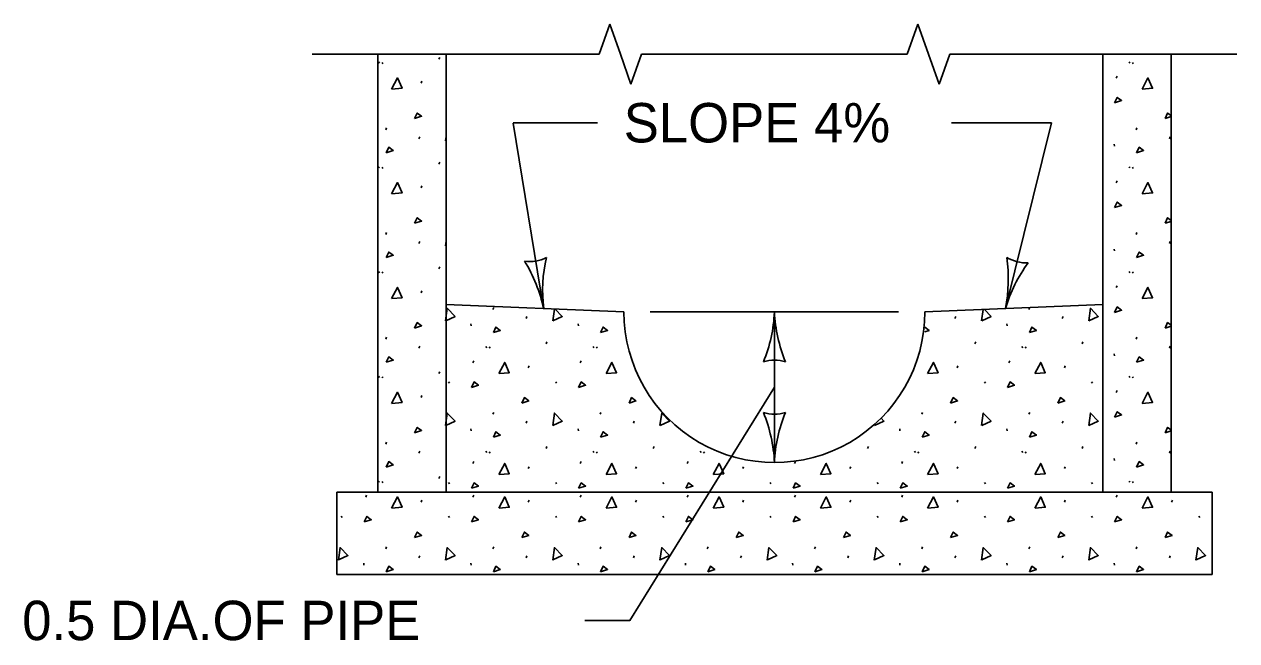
# Model space of a CAD drawing. Extents: x 49991.4 to 50028.3, y 49987.6 to 50011.4.
# Drawn here: x 50021.035 to 50022.881, y 49996.665 to 49997.603 of the extents above; entities that cross this region are included whole.
import ezdxf

# ---------------------------------------------------------------- set-up
doc = ezdxf.new("R2010")
doc.units = 0
for name, color, linetype in [('Level 1', 7, 'Continuous'), ('Level 2', 7, 'Continuous'), ('Level 3', 7, 'Continuous'), ('Level 6', 7, 'Continuous')]:
    doc.layers.add(name, color=color, linetype=linetype)

msp = doc.modelspace()

# ---------------------------------------------------------------- linework, layer by layer
at = {"layer": 'Level 1'}
for p, q in [((50021.5732, 49996.8908), (50021.5732, 49997.5575)), ((50021.6773, 49997.5575), (50021.6773, 49996.8908)), ((50022.6773, 49996.8908), (50022.6773, 49997.5575)), ((50022.7814, 49997.5575), (50022.7814, 49996.8908)), ((50021.5745, 49997.5459), (50021.5758, 49997.5439)), ((50021.5796, 49997.5451), (50021.5809, 49997.5431)), ((50021.6662, 49997.5498), (50021.6675, 49997.5528)), ((50022.7174, 49997.5459), (50022.7187, 49997.5439)), ((50022.7224, 49997.5451), (50022.7238, 49997.5431)), ((50022.6977, 49997.5212), (50022.699, 49997.5242)), ((50021.6392, 49997.5135), (50021.6405, 49997.5165)), ((50021.5852, 49997.4426), (50021.5866, 49997.4456)), ((50022.7281, 49997.4426), (50022.7294, 49997.4456)), ((50021.6358, 49997.429), (50021.6372, 49997.432)), ((50022.7787, 49997.429), (50022.78, 49997.432)), ((50022.6946, 49997.4206), (50022.695, 49997.4176)), ((50021.6662, 49997.3903), (50021.6675, 49997.3933)), ((50021.5745, 49997.3864), (50021.5758, 49997.3844)), ((50021.5796, 49997.3856), (50021.5809, 49997.3836)), ((50022.7174, 49997.3864), (50022.7187, 49997.3844)), ((50022.7224, 49997.3856), (50022.7238, 49997.3836)), ((50021.6392, 49997.3541), (50021.6405, 49997.3571)), ((50022.6977, 49997.3617), (50022.699, 49997.3647)), ((50021.5852, 49997.2832), (50021.5866, 49997.2862)), ((50022.7281, 49997.2832), (50022.7294, 49997.2862)), ((50021.6358, 49997.2695), (50021.6372, 49997.2725)), ((50022.6946, 49997.2611), (50022.695, 49997.2581)), ((50022.7787, 49997.2695), (50022.78, 49997.2725)), ((50021.5745, 49997.227), (50021.5758, 49997.225)), ((50021.5796, 49997.2262), (50021.5809, 49997.2242)), ((50021.6662, 49997.2309), (50021.6675, 49997.2338)), ((50022.7174, 49997.227), (50022.7187, 49997.225)), ((50022.7224, 49997.2262), (50022.7238, 49997.2242)), ((50022.6977, 49997.2023), (50022.699, 49997.2053)), ((50021.6392, 49997.1946), (50021.6405, 49997.1976)), ((50021.9481, 49997.1653), (50021.6773, 49997.1766)), ((50021.7485, 49997.169), (50021.7498, 49997.172)), ((50022.4064, 49997.1653), (50022.6773, 49997.1766)), ((50022.5648, 49997.169), (50022.5662, 49997.1719)), ((50021.7991, 49997.1553), (50021.8004, 49997.1583)), ((50022.4522, 49997.1553), (50022.4535, 49997.1583)), ((50022.6154, 49997.1553), (50022.6168, 49997.1583)), ((50021.715, 49997.147), (50021.7154, 49997.144)), ((50021.8783, 49997.147), (50021.8786, 49997.144)), ((50022.5314, 49997.147), (50022.5317, 49997.144)), ((50021.5852, 49997.1237), (50021.5866, 49997.1267)), ((50021.6358, 49997.11), (50021.6372, 49997.113)), ((50021.7378, 49997.1128), (50021.7391, 49997.1108)), ((50021.7428, 49997.1121), (50021.7442, 49997.1101)), ((50021.8294, 49997.1167), (50021.8308, 49997.1197)), ((50021.901, 49997.1128), (50021.9024, 49997.1108)), ((50021.9061, 49997.1121), (50021.9074, 49997.1101)), ((50022.4825, 49997.1167), (50022.4838, 49997.1197)), ((50022.5541, 49997.1128), (50022.5554, 49997.1108)), ((50022.5592, 49997.1121), (50022.5605, 49997.1101)), ((50022.6458, 49997.1167), (50022.6471, 49997.1197)), ((50022.7281, 49997.1237), (50022.7294, 49997.1267)), ((50022.7787, 49997.11), (50022.78, 49997.113)), ((50022.6946, 49997.1017), (50022.695, 49997.0987)), ((50021.6662, 49997.0714), (50021.6675, 49997.0744)), ((50021.7181, 49997.0881), (50021.7194, 49997.0911)), ((50021.8024, 49997.0805), (50021.8038, 49997.0835)), ((50021.8814, 49997.0881), (50021.8827, 49997.0911)), ((50022.4555, 49997.0805), (50022.4568, 49997.0835)), ((50022.5344, 49997.0881), (50022.5358, 49997.0911)), ((50022.6188, 49997.0805), (50022.6201, 49997.0835)), ((50021.5745, 49997.0675), (50021.5758, 49997.0655)), ((50021.5796, 49997.0668), (50021.5809, 49997.0648)), ((50021.6808, 49997.0591), (50021.6822, 49997.0571)), ((50021.8441, 49997.0591), (50021.8454, 49997.0571)), ((50022.4972, 49997.0591), (50022.4985, 49997.0571)), ((50022.6604, 49997.0591), (50022.6618, 49997.0571)), ((50022.7174, 49997.0675), (50022.7187, 49997.0655)), ((50022.7224, 49997.0668), (50022.7238, 49997.0648)), ((50021.6392, 49997.0352), (50021.6405, 49997.0382)), ((50022.6977, 49997.0428), (50022.699, 49997.0458)), ((50021.7485, 49997.0095), (50021.7498, 49997.0125)), ((50021.9118, 49997.0095), (50021.9131, 49997.0125)), ((50022.4016, 49997.0095), (50022.4029, 49997.0125)), ((50022.5648, 49997.0095), (50022.5662, 49997.0125)), ((50021.715, 49996.9875), (50021.7154, 49996.9845)), ((50021.7991, 49996.9959), (50021.8004, 49996.9989)), ((50021.8783, 49996.9875), (50021.8786, 49996.9845)), ((50021.9624, 49996.9959), (50021.9637, 49996.9989)), ((50022.3681, 49996.9875), (50022.3684, 49996.9845)), ((50022.4522, 49996.9959), (50022.4535, 49996.9989)), ((50022.5314, 49996.9875), (50022.5317, 49996.9845)), ((50022.6154, 49996.9959), (50022.6168, 49996.9989)), ((50021.5852, 49996.9642), (50021.5866, 49996.9672)), ((50022.7281, 49996.9642), (50022.7294, 49996.9672)), ((50021.6358, 49996.9506), (50021.6372, 49996.9536)), ((50021.7378, 49996.9533), (50021.7391, 49996.9513)), ((50021.7428, 49996.9526), (50021.7442, 49996.9506)), ((50021.8294, 49996.9573), (50021.8308, 49996.9603)), ((50021.901, 49996.9533), (50021.9024, 49996.9513)), ((50021.9061, 49996.9526), (50021.9074, 49996.9506)), ((50021.9927, 49996.9573), (50021.994, 49996.9603)), ((50022.0643, 49996.9533), (50022.0656, 49996.9513)), ((50022.0694, 49996.9526), (50022.0707, 49996.9506)), ((50022.3192, 49996.9573), (50022.3206, 49996.9603)), ((50022.3908, 49996.9533), (50022.3922, 49996.9513)), ((50022.3959, 49996.9526), (50022.3972, 49996.9506)), ((50022.4825, 49996.9573), (50022.4838, 49996.9603)), ((50022.5541, 49996.9533), (50022.5554, 49996.9513)), ((50022.5592, 49996.9526), (50022.5605, 49996.9506)), ((50022.6458, 49996.9573), (50022.6471, 49996.9603)), ((50022.7787, 49996.9506), (50022.78, 49996.9536)), ((50021.7181, 49996.9345), (50021.7194, 49996.9375)), ((50021.8024, 49996.9268), (50021.8038, 49996.9298)), ((50021.8814, 49996.9345), (50021.8827, 49996.9375)), ((50021.9657, 49996.9268), (50021.967, 49996.9298)), ((50022.0446, 49996.9345), (50022.046, 49996.9375)), ((50022.129, 49996.9268), (50022.1303, 49996.9298)), ((50022.2079, 49996.9345), (50022.2092, 49996.9375)), ((50022.2922, 49996.9268), (50022.2936, 49996.9298)), ((50022.3712, 49996.9345), (50022.3725, 49996.9375)), ((50022.4555, 49996.9268), (50022.4568, 49996.9298)), ((50022.6188, 49996.9268), (50022.6201, 49996.9298)), ((50022.6946, 49996.9422), (50022.695, 49996.9392)), ((50021.5745, 49996.908), (50021.5758, 49996.906)), ((50021.6662, 49996.912), (50021.6675, 49996.915)), ((50022.7174, 49996.908), (50022.7187, 49996.906)), ((50021.5106, 49996.8908), (50022.8439, 49996.8908)), ((50021.5106, 49996.8908), (50022.8439, 49996.8908)), ((50021.5106, 49996.8908), (50022.8439, 49996.8908)), ((50021.5106, 49996.7658), (50021.5106, 49996.8908)), ((50021.5796, 49996.9073), (50021.5809, 49996.9053)), ((50021.6808, 49996.9055), (50021.6822, 49996.9035)), ((50021.8441, 49996.9055), (50021.8454, 49996.9035)), ((50022.0074, 49996.9055), (50022.0087, 49996.9035)), ((50022.1706, 49996.9055), (50022.172, 49996.9035)), ((50022.3339, 49996.9055), (50022.3352, 49996.9035)), ((50022.4972, 49996.9055), (50022.4985, 49996.9035)), ((50022.6604, 49996.9055), (50022.6618, 49996.9035)), ((50022.7224, 49996.9073), (50022.7238, 49996.9053)), ((50022.8439, 49996.8908), (50022.8439, 49996.7658)), ((50021.5548, 49996.8834), (50021.5562, 49996.8864)), ((50021.6392, 49996.8757), (50021.6405, 49996.8787)), ((50021.7181, 49996.8834), (50021.7194, 49996.8864)), ((50021.8024, 49996.8757), (50021.8038, 49996.8787)), ((50021.8814, 49996.8834), (50021.8827, 49996.8864)), ((50021.9657, 49996.8757), (50021.967, 49996.8787)), ((50022.0446, 49996.8834), (50022.046, 49996.8864)), ((50022.129, 49996.8757), (50022.1303, 49996.8787)), ((50022.2079, 49996.8834), (50022.2092, 49996.8864)), ((50022.2922, 49996.8757), (50022.2936, 49996.8787)), ((50022.3712, 49996.8834), (50022.3725, 49996.8864)), ((50022.4555, 49996.8757), (50022.4568, 49996.8787)), ((50022.6188, 49996.8757), (50022.6201, 49996.8787)), ((50022.6977, 49996.8834), (50022.699, 49996.8864)), ((50022.782, 49996.8757), (50022.7834, 49996.8787)), ((50021.5176, 49996.8544), (50021.5189, 49996.8524)), ((50021.6808, 49996.8544), (50021.6822, 49996.8524)), ((50021.8441, 49996.8544), (50021.8454, 49996.8524)), ((50022.0074, 49996.8544), (50022.0087, 49996.8524)), ((50022.1706, 49996.8544), (50022.172, 49996.8524)), ((50022.3339, 49996.8544), (50022.3352, 49996.8524)), ((50022.4972, 49996.8544), (50022.4985, 49996.8524)), ((50022.6604, 49996.8544), (50022.6618, 49996.8524)), ((50022.8237, 49996.8544), (50022.825, 49996.8524)), ((50021.5852, 49996.8048), (50021.5866, 49996.8078)), ((50021.7485, 49996.8048), (50021.7498, 49996.8078)), ((50021.9118, 49996.8048), (50021.9131, 49996.8078)), ((50022.075, 49996.8048), (50022.0764, 49996.8078)), ((50022.2383, 49996.8048), (50022.2396, 49996.8078)), ((50022.4016, 49996.8048), (50022.4029, 49996.8078)), ((50022.5648, 49996.8048), (50022.5662, 49996.8078)), ((50022.7281, 49996.8048), (50022.7294, 49996.8078)), ((50021.5518, 49996.7828), (50021.5521, 49996.7798)), ((50021.6358, 49996.7911), (50021.6372, 49996.7941)), ((50021.715, 49996.7828), (50021.7154, 49996.7798)), ((50021.7991, 49996.7911), (50021.8004, 49996.7941)), ((50021.8783, 49996.7828), (50021.8786, 49996.7798)), ((50021.9624, 49996.7911), (50021.9637, 49996.7941)), ((50022.0416, 49996.7828), (50022.0419, 49996.7798)), ((50022.1256, 49996.7911), (50022.127, 49996.7941)), ((50022.2048, 49996.7828), (50022.2052, 49996.7798)), ((50022.2889, 49996.7911), (50022.2902, 49996.7941)), ((50022.3681, 49996.7828), (50022.3684, 49996.7798)), ((50022.4522, 49996.7911), (50022.4535, 49996.7941)), ((50022.5314, 49996.7828), (50022.5317, 49996.7798)), ((50022.6154, 49996.7911), (50022.6168, 49996.7941)), ((50022.6946, 49996.7828), (50022.695, 49996.7798)), ((50022.7787, 49996.7911), (50022.78, 49996.7941)), ((50022.8439, 49996.7658), (50021.5106, 49996.7658))]:
    msp.add_line(p, q, dxfattribs=at)
for points in [[(50021.5942, 49997.5046), (50021.6032, 49997.5215), (50021.6102, 49997.5059), (50021.5946, 49997.5046)], [(50022.7371, 49997.5046), (50022.7461, 49997.5215), (50022.7531, 49997.5059), (50022.7374, 49997.5046)], [(50022.6954, 49997.4836), (50022.6994, 49997.4919), (50022.706, 49997.4869), (50022.6954, 49997.4836)], [(50021.6292, 49997.4598), (50021.6332, 49997.4681), (50021.6399, 49997.4631), (50021.6292, 49997.4598)], [(50022.7721, 49997.4598), (50022.7761, 49997.4681), (50022.7814, 49997.4641)], [(50022.7814, 49997.4626), (50022.7721, 49997.4598)], [(50021.6764, 49997.4255), (50021.6773, 49997.4322)], [(50021.6773, 49997.4259), (50021.6767, 49997.4256)], [(50021.5859, 49997.4076), (50021.5899, 49997.416), (50021.5966, 49997.411), (50021.5859, 49997.4076)], [(50022.7288, 49997.4076), (50022.7328, 49997.416), (50022.7394, 49997.411), (50022.7288, 49997.4076)], [(50021.5942, 49997.3451), (50021.6032, 49997.3621), (50021.6102, 49997.3464), (50021.5946, 49997.3451)], [(50022.7371, 49997.3451), (50022.7461, 49997.3621), (50022.7531, 49997.3464), (50022.7374, 49997.3451)], [(50022.6954, 49997.3241), (50022.6994, 49997.3324), (50022.706, 49997.3274), (50022.6954, 49997.3241)], [(50021.6292, 49997.3003), (50021.6332, 49997.3086), (50021.6399, 49997.3036), (50021.6292, 49997.3003)], [(50022.7721, 49997.3003), (50022.7761, 49997.3086), (50022.7814, 49997.3046)], [(50022.7814, 49997.3032), (50022.7721, 49997.3003)], [(50021.6764, 49997.266), (50021.6773, 49997.2728)], [(50021.6773, 49997.2664), (50021.6767, 49997.2662)], [(50021.5859, 49997.2482), (50021.5899, 49997.2565), (50021.5966, 49997.2515), (50021.5859, 49997.2482)], [(50022.7288, 49997.2482), (50022.7328, 49997.2565), (50022.7394, 49997.2515), (50022.7288, 49997.2482)], [(50021.5942, 49997.1856), (50021.6032, 49997.2026), (50021.6102, 49997.187), (50021.5946, 49997.1856)], [(50022.7371, 49997.1856), (50022.7461, 49997.2026), (50022.7531, 49997.187), (50022.7374, 49997.1856)], [(50021.6764, 49997.1519), (50021.679, 49997.1709), (50021.6909, 49997.1586), (50021.6767, 49997.152)], [(50021.8396, 49997.1519), (50021.8421, 49997.1697)], [(50021.8435, 49997.1697), (50021.8542, 49997.1586), (50021.84, 49997.152)], [(50022.4927, 49997.1519), (50022.495, 49997.169)], [(50022.4971, 49997.1691), (50022.5072, 49997.1586), (50022.493, 49997.152)], [(50022.656, 49997.1519), (50022.6586, 49997.1709), (50022.6705, 49997.1586), (50022.6563, 49997.152)], [(50022.6954, 49997.1646), (50022.6994, 49997.173), (50022.706, 49997.168), (50022.6954, 49997.1646)], [(50021.6292, 49997.1408), (50021.6332, 49997.1492), (50021.6399, 49997.1442), (50021.6292, 49997.1408)], [(50022.7721, 49997.1408), (50022.7761, 49997.1492), (50022.7814, 49997.1452)], [(50021.7492, 49997.134), (50021.7532, 49997.1423), (50021.7598, 49997.1373), (50021.7492, 49997.134)], [(50021.9124, 49997.134), (50021.9164, 49997.1423), (50021.9231, 49997.1373), (50021.9124, 49997.134)], [(50022.4063, 49997.1423), (50022.4129, 49997.1373), (50022.4063, 49997.1353)], [(50022.5655, 49997.134), (50022.5695, 49997.1423), (50022.5762, 49997.1373), (50022.5655, 49997.134)], [(50022.7814, 49997.1438), (50022.7721, 49997.1408)], [(50021.9533, 49997.1135), (50021.9534, 49997.1138)], [(50021.9535, 49997.1135), (50021.9533, 49997.1135)], [(50021.5859, 49997.0887), (50021.5899, 49997.097), (50021.5966, 49997.092), (50021.5859, 49997.0887)], [(50022.7288, 49997.0887), (50022.7328, 49997.097), (50022.7394, 49997.092), (50022.7288, 49997.0887)], [(50021.7575, 49997.0715), (50021.7665, 49997.0885), (50021.7735, 49997.0728), (50021.7578, 49997.0715)], [(50021.9208, 49997.0715), (50021.9298, 49997.0885), (50021.9368, 49997.0728), (50021.9211, 49997.0715)], [(50022.4106, 49997.0715), (50022.4196, 49997.0885), (50022.4266, 49997.0728), (50022.4109, 49997.0715)], [(50022.5738, 49997.0715), (50022.5828, 49997.0885), (50022.5898, 49997.0728), (50022.5742, 49997.0715)], [(50021.7158, 49997.0505), (50021.7198, 49997.0588), (50021.7264, 49997.0538), (50021.7158, 49997.0505)], [(50021.879, 49997.0505), (50021.883, 49997.0588), (50021.8897, 49997.0538), (50021.879, 49997.0505)], [(50022.5321, 49997.0505), (50022.5361, 49997.0588), (50022.5428, 49997.0538), (50022.5321, 49997.0505)], [(50021.5942, 49997.0262), (50021.6032, 49997.0432), (50021.6102, 49997.0275), (50021.5946, 49997.0262)], [(50022.7371, 49997.0262), (50022.7461, 49997.0432), (50022.7531, 49997.0275), (50022.7374, 49997.0262)], [(50021.7925, 49997.0267), (50021.7965, 49997.035), (50021.8032, 49997.03), (50021.7925, 49997.0267)], [(50021.9558, 49997.0267), (50021.9598, 49997.035), (50021.9664, 49997.03), (50021.9558, 49997.0267)], [(50022.4456, 49997.0267), (50022.4496, 49997.035), (50022.4562, 49997.03), (50022.4456, 49997.0267)], [(50022.6088, 49997.0267), (50022.6128, 49997.035), (50022.6195, 49997.03), (50022.6088, 49997.0267)], [(50021.6764, 49996.9924), (50021.679, 49997.0115), (50021.6909, 49996.9991), (50021.6767, 49996.9925)], [(50021.8396, 49996.9924), (50021.8423, 49997.0115), (50021.8542, 49996.9991), (50021.84, 49996.9925)], [(50022.0029, 49996.9924), (50022.0056, 49997.0115), (50022.0175, 49996.9991), (50022.0032, 49996.9925)], [(50022.3397, 49997.0036), (50022.344, 49996.9991), (50022.3298, 49996.9925)], [(50022.4927, 49996.9924), (50022.4953, 49997.0115), (50022.5072, 49996.9991), (50022.493, 49996.9925)], [(50022.656, 49996.9924), (50022.6586, 49997.0115), (50022.6705, 49996.9991), (50022.6563, 49996.9925)], [(50022.6954, 49997.0052), (50022.6994, 49997.0135), (50022.706, 49997.0085), (50022.6954, 49997.0052)], [(50021.6292, 49996.9814), (50021.6332, 49996.9897), (50021.6399, 49996.9847), (50021.6292, 49996.9814)], [(50021.7492, 49996.9746), (50021.7532, 49996.9829), (50021.7598, 49996.9779), (50021.7492, 49996.9746)], [(50021.9124, 49996.9746), (50021.9164, 49996.9829), (50021.9231, 49996.9779), (50021.9124, 49996.9746)], [(50022.3294, 49996.9924), (50022.3296, 49996.9933)], [(50022.4022, 49996.9746), (50022.4062, 49996.9829), (50022.4129, 49996.9779), (50022.4022, 49996.9746)], [(50022.5655, 49996.9746), (50022.5695, 49996.9829), (50022.5762, 49996.9779), (50022.5655, 49996.9746)], [(50022.7721, 49996.9814), (50022.7761, 49996.9897), (50022.7814, 49996.9858)], [(50022.7814, 49996.9843), (50022.7721, 49996.9814)], [(50021.5859, 49996.9293), (50021.5899, 49996.9376), (50021.5966, 49996.9326), (50021.5859, 49996.9293)], [(50021.7575, 49996.9178), (50021.7665, 49996.9348), (50021.7735, 49996.9191), (50021.7578, 49996.9178)], [(50021.9208, 49996.9178), (50021.9298, 49996.9348), (50021.9368, 49996.9191), (50021.9211, 49996.9178)], [(50022.084, 49996.9178), (50022.093, 49996.9348), (50022.1, 49996.9191), (50022.0844, 49996.9178)], [(50022.2473, 49996.9178), (50022.2563, 49996.9348), (50022.2633, 49996.9191), (50022.2476, 49996.9178)], [(50022.4106, 49996.9178), (50022.4196, 49996.9348), (50022.4266, 49996.9191), (50022.4109, 49996.9178)], [(50022.5738, 49996.9178), (50022.5828, 49996.9348), (50022.5898, 49996.9191), (50022.5742, 49996.9178)], [(50022.7288, 49996.9293), (50022.7328, 49996.9376), (50022.7394, 49996.9326), (50022.7288, 49996.9293)], [(50021.7158, 49996.8969), (50021.7198, 49996.9052), (50021.7264, 49996.9002), (50021.7158, 49996.8969)], [(50021.879, 49996.8969), (50021.883, 49996.9052), (50021.8897, 49996.9002), (50021.879, 49996.8969)], [(50022.0423, 49996.8969), (50022.0463, 49996.9052), (50022.053, 49996.9002), (50022.0423, 49996.8969)], [(50022.2056, 49996.8969), (50022.2096, 49996.9052), (50022.2162, 49996.9002), (50022.2056, 49996.8969)], [(50022.3688, 49996.8969), (50022.3728, 49996.9052), (50022.3795, 49996.9002), (50022.3688, 49996.8969)], [(50022.5321, 49996.8969), (50022.5361, 49996.9052), (50022.5428, 49996.9002), (50022.5321, 49996.8969)], [(50021.5942, 49996.8667), (50021.6032, 49996.8837), (50021.6102, 49996.868), (50021.5946, 49996.8667)], [(50021.7575, 49996.8667), (50021.7665, 49996.8837), (50021.7735, 49996.868), (50021.7578, 49996.8667)], [(50021.9208, 49996.8667), (50021.9298, 49996.8837), (50021.9368, 49996.868), (50021.9211, 49996.8667)], [(50022.084, 49996.8667), (50022.093, 49996.8837), (50022.1, 49996.868), (50022.0844, 49996.8667)], [(50022.2473, 49996.8667), (50022.2563, 49996.8837), (50022.2633, 49996.868), (50022.2476, 49996.8667)], [(50022.4106, 49996.8667), (50022.4196, 49996.8837), (50022.4266, 49996.868), (50022.4109, 49996.8667)], [(50022.5738, 49996.8667), (50022.5828, 49996.8837), (50022.5898, 49996.868), (50022.5742, 49996.8667)], [(50022.7371, 49996.8667), (50022.7461, 49996.8837), (50022.7531, 49996.868), (50022.7374, 49996.8667)], [(50021.5525, 49996.8458), (50021.5565, 49996.8541), (50021.5632, 49996.8491), (50021.5525, 49996.8458)], [(50021.7158, 49996.8458), (50021.7198, 49996.8541), (50021.7264, 49996.8491), (50021.7158, 49996.8458)], [(50021.879, 49996.8458), (50021.883, 49996.8541), (50021.8897, 49996.8491), (50021.879, 49996.8458)], [(50022.0423, 49996.8458), (50022.0463, 49996.8541), (50022.053, 49996.8491), (50022.0423, 49996.8458)], [(50022.2056, 49996.8458), (50022.2096, 49996.8541), (50022.2162, 49996.8491), (50022.2056, 49996.8458)], [(50022.3688, 49996.8458), (50022.3728, 49996.8541), (50022.3795, 49996.8491), (50022.3688, 49996.8458)], [(50022.5321, 49996.8458), (50022.5361, 49996.8541), (50022.5428, 49996.8491), (50022.5321, 49996.8458)], [(50022.6954, 49996.8458), (50022.6994, 49996.8541), (50022.706, 49996.8491), (50022.6954, 49996.8458)], [(50021.6292, 49996.8219), (50021.6332, 49996.8302), (50021.6399, 49996.8253), (50021.6292, 49996.8219)], [(50021.7925, 49996.8219), (50021.7965, 49996.8302), (50021.8032, 49996.8253), (50021.7925, 49996.8219)], [(50021.9558, 49996.8219), (50021.9598, 49996.8302), (50021.9664, 49996.8253), (50021.9558, 49996.8219)], [(50022.119, 49996.8219), (50022.123, 49996.8302), (50022.1297, 49996.8253), (50022.119, 49996.8219)], [(50022.2823, 49996.8219), (50022.2863, 49996.8302), (50022.293, 49996.8253), (50022.2823, 49996.8219)], [(50022.4456, 49996.8219), (50022.4496, 49996.8302), (50022.4562, 49996.8253), (50022.4456, 49996.8219)], [(50022.6088, 49996.8219), (50022.6128, 49996.8302), (50022.6195, 49996.8253), (50022.6088, 49996.8219)], [(50022.7721, 49996.8219), (50022.7761, 49996.8302), (50022.7828, 49996.8253), (50022.7721, 49996.8219)], [(50021.5131, 49996.7877), (50021.5158, 49996.8067), (50021.5277, 49996.7944), (50021.5134, 49996.7878)], [(50021.6764, 49996.7877), (50021.679, 49996.8067), (50021.6909, 49996.7944), (50021.6767, 49996.7878)], [(50021.8396, 49996.7877), (50021.8423, 49996.8067), (50021.8542, 49996.7944), (50021.84, 49996.7878)], [(50022.0029, 49996.7877), (50022.0056, 49996.8067), (50022.0175, 49996.7944), (50022.0032, 49996.7878)], [(50022.1662, 49996.7877), (50022.1688, 49996.8067), (50022.1807, 49996.7944), (50022.1665, 49996.7878)], [(50022.3294, 49996.7877), (50022.3321, 49996.8067), (50022.344, 49996.7944), (50022.3298, 49996.7878)], [(50022.4927, 49996.7877), (50022.4953, 49996.8067), (50022.5072, 49996.7944), (50022.493, 49996.7878)], [(50022.656, 49996.7877), (50022.6586, 49996.8067), (50022.6705, 49996.7944), (50022.6563, 49996.7878)], [(50022.8192, 49996.7877), (50022.8219, 49996.8067), (50022.8338, 49996.7944), (50022.8196, 49996.7878)], [(50021.5859, 49996.7698), (50021.5899, 49996.7782), (50021.5966, 49996.7732), (50021.5859, 49996.7698)], [(50021.7492, 49996.7698), (50021.7532, 49996.7782), (50021.7598, 49996.7732), (50021.7492, 49996.7698)], [(50021.9124, 49996.7698), (50021.9164, 49996.7782), (50021.9231, 49996.7732), (50021.9124, 49996.7698)], [(50022.0757, 49996.7698), (50022.0797, 49996.7782), (50022.0864, 49996.7732), (50022.0757, 49996.7698)], [(50022.239, 49996.7698), (50022.243, 49996.7782), (50022.2496, 49996.7732), (50022.239, 49996.7698)], [(50022.4022, 49996.7698), (50022.4062, 49996.7782), (50022.4129, 49996.7732), (50022.4022, 49996.7698)], [(50022.5655, 49996.7698), (50022.5695, 49996.7782), (50022.5762, 49996.7732), (50022.5655, 49996.7698)], [(50022.7288, 49996.7698), (50022.7328, 49996.7782), (50022.7394, 49996.7732), (50022.7288, 49996.7698)], [(50022.8348, 49996.766), (50022.8347, 49996.7658)]]:
    msp.add_lwpolyline(points, dxfattribs=at)
msp.add_arc((50022.1773, 49997.1653), 0.2292, 180, 0.0005, dxfattribs=at)
at = {"layer": 'Level 3'}
for p, q in [((50021.9077, 49997.4533), (50021.7791, 49997.4533)), ((50021.8258, 49997.1704), (50021.7791, 49997.4524)), ((50022.447, 49997.4533), (50022.5992, 49997.4533)), ((50022.5992, 49997.4532), (50022.5291, 49997.1704)), ((50021.9881, 49997.1653), (50022.3664, 49997.1653)), ((50022.1773, 49997.1653), (50022.1773, 49996.9362))]:
    msp.add_line(p, q, dxfattribs=at)
msp.add_lwpolyline([(50021.8884, 49996.6958), (50021.9572, 49996.6958), (50022.1773, 49997.0507)], dxfattribs=at)
for centre, radius, start, end in [((50021.8049, 49997.2969), 0.0548, 261.5504, 297.2728), ((50021.5981, 49997.121), 0.233, 12.2389, 31.4887), ((50022.0465, 49997.1977), 0.2223, 166.8676, 187.0511), ((50022.3005, 49997.2153), 0.233, 348.9053, 8.1552), ((50022.7425, 49997.1081), 0.2223, 143.534, 163.7175), ((50022.56, 49997.2949), 0.0548, 238.2168, 273.9392), ((50021.9551, 49997.1745), 0.2223, 337.456, 357.6395), ((50022.41, 49997.1768), 0.233, 182.8273, 202.0772), ((50022.1773, 49997.0371), 0.0548, 72.1388, 107.8612), ((50022.1773, 49997.0644), 0.0548, 252.1388, 287.8612), ((50021.9446, 49996.9247), 0.233, 2.8273, 22.0772), ((50022.3994, 49996.927), 0.2223, 157.456, 177.6395)]:
    msp.add_arc(centre, radius, start, end, dxfattribs=at)
at = {"layer": 'Level 6'}
for p, q in [((50021.9264, 49997.6032), (50021.9102, 49997.5575)), ((50021.9264, 49997.6032), (50021.9426, 49997.5575)), ((50022.3958, 49997.6032), (50022.3796, 49997.5575)), ((50022.3958, 49997.6032), (50022.412, 49997.5575)), ((50021.4732, 49997.5575), (50021.9102, 49997.5575)), ((50021.9426, 49997.5575), (50021.9588, 49997.5118)), ((50021.975, 49997.5575), (50021.9588, 49997.5118)), ((50021.975, 49997.5575), (50022.3796, 49997.5575)), ((50022.412, 49997.5575), (50022.4282, 49997.5118)), ((50022.4444, 49997.5575), (50022.4282, 49997.5118)), ((50022.4444, 49997.5575), (50022.8814, 49997.5575))]:
    msp.add_line(p, q, dxfattribs=at)

# ---------------------------------------------------------------- texts
at = {"layer": 'Level 2'}
for s, p in [('SLOPE 4%', (50021.9477, 49997.4233)), ('0.5 DIA.OF PIPE', (50021.0316, 49996.6658))]:
    msp.add_text(s, height=0.06, dxfattribs=at).set_placement(p)

doc.saveas('drawing.dxf')
